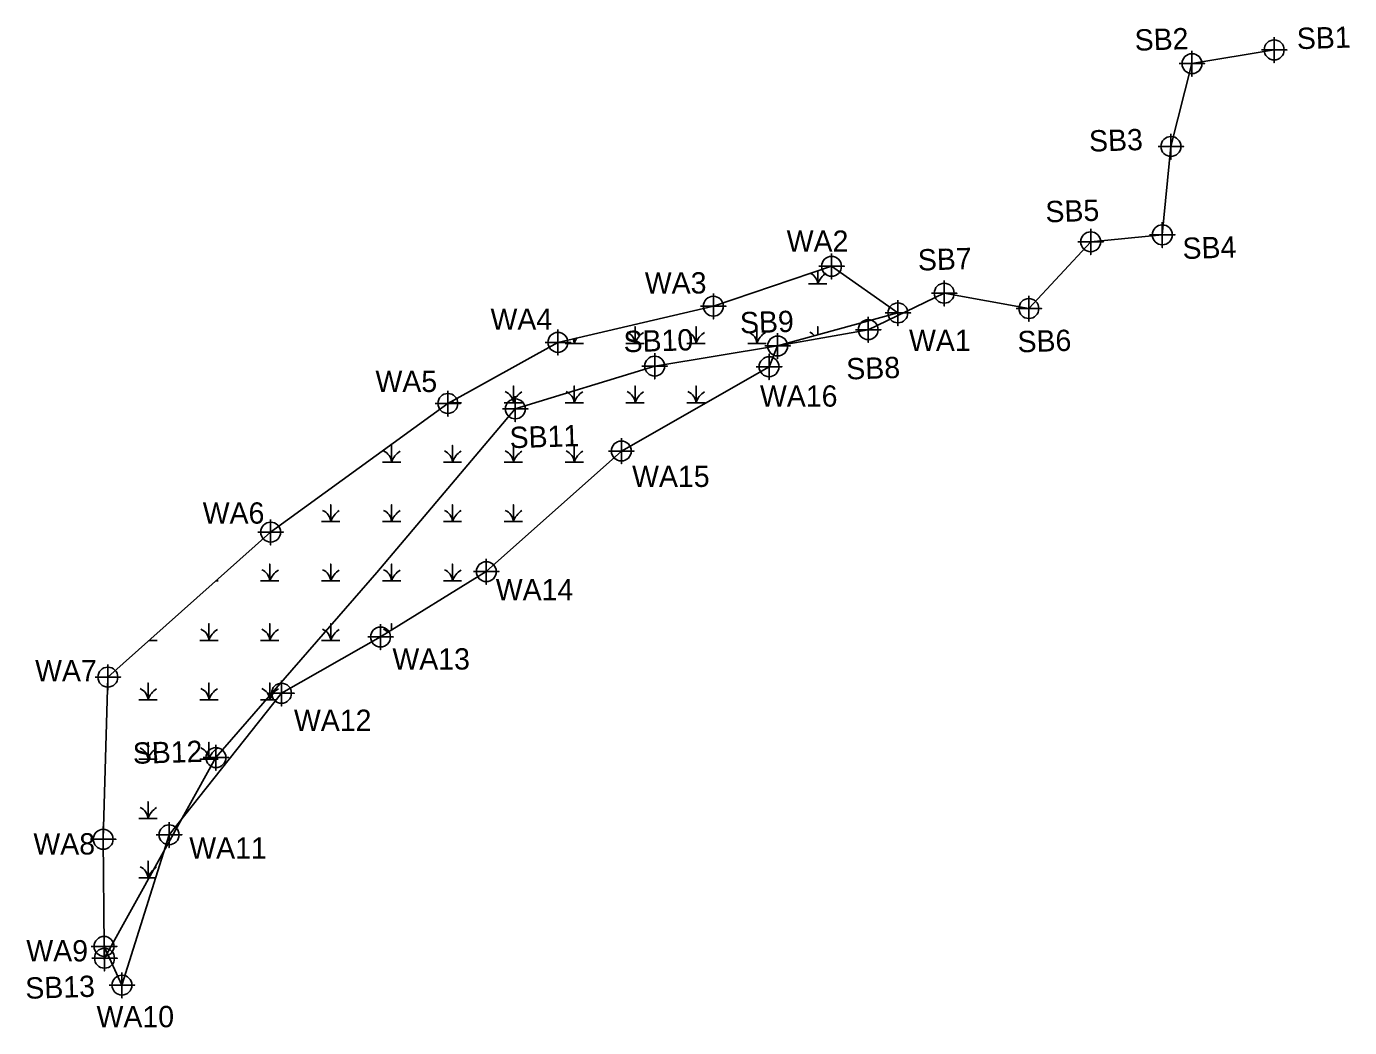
# Model space of a CAD drawing. Extents: x 1616941 to 1621864, y 896903 to 900301.
# Drawn here: x 1619876.1 to 1620186.9, y 898877.1 to 899112.1 of the extents above; entities that cross this region are included whole.
import ezdxf

# ---------------------------------------------------------------- set-up
doc = ezdxf.new("R2010")
doc.units = 0
for name, color, linetype in [('Exist Hydro Swamp or Marsh', 7, 'Continuous'), ('Sheet Block Revision CELL', 7, 'Continuous'), ('Sheet Layout Plan Border', 7, 'Continuous'), ('Sheet North Arrow Point CELL', 7, 'Continuous'), ('Sheet Plan CELL', 7, 'Continuous'), ('Sheet Plot Border Outside CELL', 7, 'Continuous'), ('Sheet Sticker Exception Certification CELL', 7, 'Continuous')]:
    doc.layers.add(name, color=color, linetype=linetype)

msp = doc.modelspace()

# ---------------------------------------------------------------- linework, layer by layer
at = {"layer": 'Exist Hydro Swamp or Marsh'}
for p, q in [((1619920.58, 898981.92), (1619921.1, 898981.92)), ((1619904.92, 898967.97), (1619906.8, 898967.97))]:
    msp.add_line(p, q, dxfattribs=at)
for points in [[(1620059.81, 899051.64), (1620061.96, 899051.64), (1620061.96, 899054.7)], [(1620061.96, 899054.7), (1620061.96, 899051.64), (1620064.11, 899051.64)], [(1620016.91, 899037.7), (1620019.06, 899037.7), (1620019.06, 899041.64), (1620019.06, 899037.7), (1620021.21, 899037.7)], [(1620031.21, 899037.7), (1620033.36, 899037.7), (1620033.36, 899041.64), (1620033.36, 899037.7), (1620035.51, 899037.7)], [(1620045.51, 899037.7), (1620047.66, 899037.7), (1620047.66, 899041.64), (1620047.66, 899037.7), (1620049.81, 899037.7)], [(1620061.96, 899039.67), (1620061.96, 899041.64), (1620061.96, 899039.67)], [(1620002.61, 899037.7), (1620004.76, 899037.7), (1620004.76, 899038.82)], [(1620004.76, 899038.82), (1620004.76, 899037.7), (1620006.91, 899037.7)], [(1619988.31, 899023.75), (1619990.46, 899023.75), (1619990.46, 899027.7), (1619990.46, 899023.75), (1619992.61, 899023.75)], [(1620002.61, 899023.75), (1620004.76, 899023.75), (1620004.76, 899027.7), (1620004.76, 899023.75), (1620006.91, 899023.75)], [(1620016.91, 899023.75), (1620019.06, 899023.75), (1620019.06, 899027.7), (1620019.06, 899023.75), (1620021.21, 899023.75)], [(1620031.21, 899023.75), (1620033.36, 899023.75), (1620033.36, 899027.7), (1620033.36, 899023.75), (1620035.51, 899023.75)], [(1619975.35, 899023.75), (1619976.16, 899023.75), (1619976.16, 899024.2)], [(1619976.16, 899024.2), (1619976.16, 899023.75), (1619978.31, 899023.75)], [(1619959.71, 899009.81), (1619961.86, 899009.81), (1619961.86, 899013.75), (1619961.86, 899009.81), (1619964.01, 899009.81)], [(1619974.01, 899009.81), (1619976.16, 899009.81), (1619976.16, 899013.75), (1619976.16, 899009.81), (1619978.31, 899009.81)], [(1619988.31, 899009.81), (1619990.46, 899009.81), (1619990.46, 899013.75), (1619990.46, 899009.81), (1619992.61, 899009.81)], [(1620002.61, 899009.81), (1620004.76, 899009.81), (1620004.76, 899013.75), (1620004.76, 899009.81), (1620006.91, 899009.81)], [(1619945.4, 898995.86), (1619947.55, 898995.86), (1619947.55, 898999.81), (1619947.55, 898995.86), (1619949.71, 898995.86)], [(1619959.71, 898995.86), (1619961.86, 898995.86), (1619961.86, 898999.81), (1619961.86, 898995.86), (1619964.01, 898995.86)], [(1619974.01, 898995.86), (1619976.16, 898995.86), (1619976.16, 898999.81), (1619976.16, 898995.86), (1619978.31, 898995.86)], [(1619988.31, 898995.86), (1619990.46, 898995.86), (1619990.46, 898999.81), (1619990.46, 898995.86), (1619992.61, 898995.86)], [(1619931.1, 898981.92), (1619933.25, 898981.92), (1619933.25, 898985.86), (1619933.25, 898981.92), (1619935.4, 898981.92)], [(1619945.4, 898981.92), (1619947.55, 898981.92), (1619947.55, 898985.86), (1619947.55, 898981.92), (1619949.71, 898981.92)], [(1619959.71, 898981.92), (1619961.86, 898981.92), (1619961.86, 898985.86), (1619961.86, 898981.92), (1619964.01, 898981.92)], [(1619974.01, 898981.92), (1619976.16, 898981.92), (1619976.16, 898985.86), (1619976.16, 898981.92), (1619978.31, 898981.92)], [(1619916.8, 898967.97), (1619918.95, 898967.97), (1619918.95, 898971.92), (1619918.95, 898967.97), (1619921.1, 898967.97)], [(1619931.1, 898967.97), (1619933.25, 898967.97), (1619933.25, 898971.92), (1619933.25, 898967.97), (1619935.4, 898967.97)], [(1619945.4, 898967.97), (1619947.55, 898967.97), (1619947.55, 898971.92), (1619947.55, 898967.97), (1619949.71, 898967.97)], [(1619961.86, 898970.36), (1619961.86, 898971.92), (1619961.86, 898970.36)], [(1619902.5, 898954.03), (1619904.65, 898954.03), (1619904.65, 898957.97), (1619904.65, 898954.03), (1619906.8, 898954.03)], [(1619916.8, 898954.03), (1619918.95, 898954.03), (1619918.95, 898957.97), (1619918.95, 898954.03), (1619921.1, 898954.03)], [(1619931.1, 898954.03), (1619933.25, 898954.03), (1619933.25, 898957.97), (1619933.25, 898954.03), (1619934.78, 898954.03)], [(1619902.5, 898940.08), (1619904.65, 898940.08), (1619904.65, 898944.03), (1619904.65, 898940.08), (1619906.8, 898940.08)], [(1619916.8, 898940.08), (1619918.95, 898940.08), (1619918.95, 898944.03), (1619918.95, 898940.08), (1619921.1, 898940.08)], [(1619902.5, 898926.14), (1619904.65, 898926.14), (1619904.65, 898930.08), (1619904.65, 898926.14), (1619906.8, 898926.14)], [(1619902.5, 898912.19), (1619904.65, 898912.19), (1619904.65, 898916.14), (1619904.65, 898912.19), (1619906.42, 898912.19)]]:
    msp.add_lwpolyline(points, dxfattribs=at)
for centre, radius, start, end in [((1620058.89, 899051.42), 3.07, 4.1403, 62.3561), ((1620066.52, 899050.13), 4.81, 122.1274, 161.6222), ((1620015.99, 899037.48), 3.07, 4.1403, 67.535), ((1620023.62, 899036.18), 4.81, 122.1274, 161.6222), ((1620030.29, 899037.48), 3.07, 4.1403, 67.535), ((1620037.92, 899036.18), 4.81, 122.1274, 161.6222), ((1620044.59, 899037.48), 3.07, 4.1403, 67.535), ((1620052.22, 899036.18), 4.81, 122.1274, 161.6222), ((1620058.89, 899037.48), 3.07, 40.5332, 67.535), ((1620066.52, 899036.18), 4.81, 122.1274, 123.1628), ((1620001.69, 899037.48), 3.07, 4.1403, 24.6424), ((1620009.32, 899036.18), 4.81, 144.5287, 161.6222), ((1619973.09, 899023.53), 3.07, 4.1403, 11.9211), ((1619980.72, 899022.24), 4.81, 154.2231, 161.6222), ((1619987.39, 899023.53), 3.07, 4.1403, 67.535), ((1619995.02, 899022.24), 4.81, 122.1274, 161.6222), ((1620001.69, 899023.53), 3.07, 4.1403, 67.535), ((1620009.32, 899022.24), 4.81, 122.1274, 161.6222), ((1620015.99, 899023.53), 3.07, 4.1403, 67.535), ((1620023.62, 899022.24), 4.81, 122.1274, 161.6222), ((1620030.29, 899023.53), 3.07, 4.1403, 67.535), ((1620037.92, 899022.24), 4.81, 122.1274, 161.6222), ((1619958.79, 899009.59), 3.07, 4.1403, 67.535), ((1619966.42, 899008.29), 4.81, 122.1274, 161.6222), ((1619973.09, 899009.59), 3.07, 4.1403, 67.535), ((1619980.72, 899008.29), 4.81, 122.1274, 161.6222), ((1619987.39, 899009.59), 3.07, 4.1403, 67.535), ((1619995.02, 899008.29), 4.81, 122.1274, 161.6222), ((1620001.69, 899009.59), 3.07, 4.1403, 67.535), ((1620009.32, 899008.29), 4.81, 122.1274, 161.6222), ((1619944.49, 898995.64), 3.07, 4.1403, 67.535), ((1619952.12, 898994.35), 4.81, 122.1274, 161.6222), ((1619958.79, 898995.64), 3.07, 4.1403, 67.535), ((1619966.42, 898994.35), 4.81, 122.1274, 161.6222), ((1619973.09, 898995.64), 3.07, 4.1403, 67.535), ((1619980.72, 898994.35), 4.81, 122.1274, 161.6222), ((1619987.39, 898995.64), 3.07, 4.1403, 67.535), ((1619995.02, 898994.35), 4.81, 122.1274, 161.6222), ((1619930.19, 898981.7), 3.07, 4.1403, 67.535), ((1619937.81, 898980.4), 4.81, 122.1274, 161.6222), ((1619944.49, 898981.7), 3.07, 4.1403, 67.535), ((1619952.12, 898980.4), 4.81, 122.1274, 161.6222), ((1619958.79, 898981.7), 3.07, 4.1403, 67.535), ((1619966.42, 898980.4), 4.81, 122.1274, 161.6222), ((1619973.09, 898981.7), 3.07, 4.1403, 67.535), ((1619980.72, 898980.4), 4.81, 122.1274, 161.6222), ((1619915.89, 898967.75), 3.07, 4.1403, 67.535), ((1619923.51, 898966.46), 4.81, 122.1274, 161.6222), ((1619930.19, 898967.75), 3.07, 4.1403, 67.535), ((1619937.81, 898966.46), 4.81, 122.1274, 161.6222), ((1619944.49, 898967.75), 3.07, 4.1403, 67.535), ((1619952.12, 898966.46), 4.81, 122.1274, 161.6222), ((1619958.79, 898967.75), 3.07, 43.1793, 67.535), ((1619901.59, 898953.81), 3.07, 4.1403, 67.535), ((1619909.21, 898952.51), 4.81, 122.1274, 161.6222), ((1619915.89, 898953.81), 3.07, 4.1403, 67.535), ((1619923.51, 898952.51), 4.81, 122.1274, 161.6222), ((1619930.19, 898953.81), 3.07, 4.1403, 67.535), ((1619937.81, 898952.51), 4.81, 122.1274, 161.6222), ((1619901.59, 898939.86), 3.07, 4.1403, 67.535), ((1619909.21, 898938.57), 4.81, 122.1274, 161.6222), ((1619915.89, 898939.86), 3.07, 4.1403, 67.535), ((1619923.51, 898938.57), 4.81, 122.1274, 161.6222), ((1619901.59, 898925.91), 3.07, 4.1403, 67.535), ((1619909.21, 898924.62), 4.81, 122.1274, 161.6222), ((1619901.59, 898911.97), 3.07, 4.1403, 67.535), ((1619909.21, 898910.68), 4.81, 122.1274, 161.6222), ((1619901.59, 898898.02), 3.07, 65.6983, 67.535)]:
    msp.add_arc(centre, radius, start, end, dxfattribs=at)
at = {"layer": 'Sheet Block Revision CELL'}
msp.add_lwpolyline([(1620080.78, 899044.85), (1620052.53, 899037.08), (1620050.52, 899032.21), (1620015.82, 899012.42), (1619984.1, 898984.1), (1619959.26, 898968.76), (1619936, 898955.55), (1619909.59, 898922.31), (1619898.52, 898887.02), (1619894.32, 898896.11), (1619894.12, 898921.26), (1619895.21, 898959.33), (1619933.45, 898993.38), (1619975.07, 899023.59), (1620000.92, 899037.93), (1620037.43, 899046.42), (1620065.2, 899055.79)], close=True, dxfattribs=at)
at = {"layer": 'Sheet North Arrow Point CELL'}
for points in [[(1620169.16, 899109.6), (1620169.16, 899103.6), (1620169.16, 899106.6), (1620172.16, 899106.6), (1620166.16, 899106.6)], [(1620149.86, 899106.37), (1620149.86, 899100.37), (1620149.86, 899103.37), (1620152.86, 899103.37), (1620146.86, 899103.37)], [(1620144.91, 899086.93), (1620144.91, 899080.93), (1620144.91, 899083.93), (1620147.91, 899083.93), (1620141.91, 899083.93)], [(1620126.07, 899064.55), (1620126.07, 899058.55), (1620126.07, 899061.55), (1620129.07, 899061.55), (1620123.07, 899061.55)], [(1620142.89, 899066.18), (1620142.89, 899060.18), (1620142.89, 899063.18), (1620145.89, 899063.18), (1620139.89, 899063.18)], [(1620091.66, 899052.47), (1620091.66, 899046.47), (1620091.66, 899049.47), (1620094.66, 899049.47), (1620088.66, 899049.47)], [(1620111.54, 899048.87), (1620111.54, 899042.87), (1620111.54, 899045.87), (1620114.54, 899045.87), (1620108.54, 899045.87)], [(1620073.81, 899043.91), (1620073.81, 899037.91), (1620073.81, 899040.91), (1620076.81, 899040.91), (1620070.81, 899040.91)], [(1620052.53, 899040.08), (1620052.53, 899034.08), (1620052.53, 899037.08), (1620055.53, 899037.08), (1620049.53, 899037.08)], [(1620023.66, 899035.36), (1620023.66, 899029.36), (1620023.66, 899032.36), (1620026.66, 899032.36), (1620020.66, 899032.36)], [(1619990.92, 899025.31), (1619990.92, 899019.31), (1619990.92, 899022.31), (1619993.92, 899022.31), (1619987.92, 899022.31)], [(1619920.59, 898943.44), (1619920.59, 898937.44), (1619920.59, 898940.44), (1619923.59, 898940.44), (1619917.59, 898940.44)], [(1619894.42, 898896.34), (1619894.42, 898890.34), (1619894.42, 898893.34), (1619897.42, 898893.34), (1619891.42, 898893.34)]]:
    msp.add_lwpolyline(points, dxfattribs=at)
for centre in [(1620169.16, 899106.6), (1620149.86, 899103.37), (1620144.91, 899083.93), (1620142.89, 899063.18), (1620126.07, 899061.55), (1620091.66, 899049.47), (1620111.54, 899045.87), (1620073.81, 899040.91), (1620052.53, 899037.08), (1620023.66, 899032.36), (1619990.92, 899022.31), (1619920.59, 898940.44), (1619894.42, 898893.34)]:
    msp.add_circle(centre, 2.34, dxfattribs=at)
at = {"layer": 'Sheet Plan CELL'}
for points in [[(1620065.2, 899058.79), (1620065.2, 899052.79), (1620065.2, 899055.79), (1620068.2, 899055.79), (1620062.2, 899055.79)], [(1620037.43, 899049.42), (1620037.43, 899043.42), (1620037.43, 899046.42), (1620040.43, 899046.42), (1620034.43, 899046.42)], [(1620080.78, 899047.85), (1620080.78, 899041.85), (1620080.78, 899044.85), (1620083.78, 899044.85), (1620077.78, 899044.85)], [(1620000.92, 899040.93), (1620000.92, 899034.93), (1620000.92, 899037.93), (1620003.92, 899037.93), (1619997.92, 899037.93)], [(1620050.52, 899035.21), (1620050.52, 899029.21), (1620050.52, 899032.21), (1620053.52, 899032.21), (1620047.52, 899032.21)], [(1619975.07, 899026.59), (1619975.07, 899020.59), (1619975.07, 899023.59), (1619978.07, 899023.59), (1619972.07, 899023.59)], [(1620015.82, 899015.42), (1620015.82, 899009.42), (1620015.82, 899012.42), (1620018.82, 899012.42), (1620012.82, 899012.42)], [(1619933.45, 898996.38), (1619933.45, 898990.38), (1619933.45, 898993.38), (1619936.45, 898993.38), (1619930.45, 898993.38)], [(1619984.1, 898987.1), (1619984.1, 898981.1), (1619984.1, 898984.1), (1619987.1, 898984.1), (1619981.1, 898984.1)], [(1619959.26, 898971.76), (1619959.26, 898965.76), (1619959.26, 898968.76), (1619962.26, 898968.76), (1619956.26, 898968.76)], [(1619895.21, 898962.33), (1619895.21, 898956.33), (1619895.21, 898959.33), (1619898.21, 898959.33), (1619892.21, 898959.33)], [(1619936, 898958.55), (1619936, 898952.55), (1619936, 898955.55), (1619939, 898955.55), (1619933, 898955.55)], [(1619909.59, 898925.31), (1619909.59, 898919.31), (1619909.59, 898922.31), (1619912.59, 898922.31), (1619906.59, 898922.31)], [(1619894.12, 898924.26), (1619894.12, 898918.26), (1619894.12, 898921.26), (1619897.12, 898921.26), (1619891.12, 898921.26)], [(1619894.32, 898899.11), (1619894.32, 898893.11), (1619894.32, 898896.11), (1619897.32, 898896.11), (1619891.32, 898896.11)], [(1619898.52, 898890.02), (1619898.52, 898884.02), (1619898.52, 898887.02), (1619901.52, 898887.02), (1619895.52, 898887.02)]]:
    msp.add_lwpolyline(points, dxfattribs=at)
for centre in [(1620065.2, 899055.79), (1620037.43, 899046.42), (1620080.78, 899044.85), (1620000.92, 899037.93), (1620050.52, 899032.21), (1619975.07, 899023.59), (1620015.82, 899012.42), (1619933.45, 898993.38), (1619984.1, 898984.1), (1619959.26, 898968.76), (1619895.21, 898959.33), (1619936, 898955.55), (1619909.59, 898922.31), (1619894.12, 898921.26), (1619894.32, 898896.11), (1619898.52, 898887.02)]:
    msp.add_circle(centre, 2.34, dxfattribs=at)
at = {"layer": 'Sheet Sticker Exception Certification CELL'}
for points in [[(1620169.16, 899106.6), (1620149.86, 899103.37), (1620144.91, 899083.93), (1620142.89, 899063.18), (1620126.07, 899061.55), (1620111.54, 899045.87), (1620091.66, 899049.47), (1620073.81, 899040.91), (1620052.53, 899037.08), (1620023.66, 899032.36)], [(1620023.66, 899032.36), (1619990.92, 899022.31), (1619958.4, 898983.88), (1619920.59, 898940.44), (1619894.42, 898893.34)]]:
    msp.add_lwpolyline(points, dxfattribs=at)

# ---------------------------------------------------------------- texts
at = {"layer": 'Sheet Layout Plan Border'}
for s, p in [('SB2', (1620136.47, 899106.4)), ('SB1', (1620174.56, 899106.76)), ('SB3', (1620125.75, 899082.7)), ('SB5', (1620115.51, 899066.1)), ('SB4', (1620147.7, 899057.49)), ('SB7', (1620085.54, 899054.77)), ('SB9', (1620043.76, 899040.02)), ('SB10', (1620016.42, 899035.59)), ('SB6', (1620108.95, 899035.57)), ('SB8', (1620068.73, 899029.2)), ('SB11', (1619989.65, 899013.07)), ('SB12', (1619901.14, 898938.95)), ('SB13', (1619875.89, 898883.79))]:
    msp.add_text(s, height=5, rotation=1.7576, dxfattribs=at).set_placement(p)
at = {"layer": 'Sheet Plot Border Outside CELL'}
for s, p in [('WA2', (1620054.66, 899059.2)), ('WA3', (1620021.33, 899049.4)), ('WA4', (1619985.09, 899040.88)), ('WA1', (1620083.39, 899035.89)), ('WA5', (1619958.07, 899026.27)), ('WA16', (1620048.38, 899022.84)), ('WA15', (1620018.35, 899003.99)), ('WA6', (1619917.49, 898995.37)), ('WA14', (1619986.33, 898977.37)), ('WA13', (1619962.05, 898961.11)), ('WA7', (1619878.12, 898958.37)), ('WA12', (1619938.92, 898946.7)), ('WA8', (1619877.72, 898917.68)), ('WA11', (1619914.33, 898916.72)), ('WA9', (1619876.06, 898892.58)), ('WA10', (1619892.55, 898877.13))]:
    msp.add_text(s, height=5, dxfattribs=at).set_placement(p)

doc.saveas('drawing.dxf')
